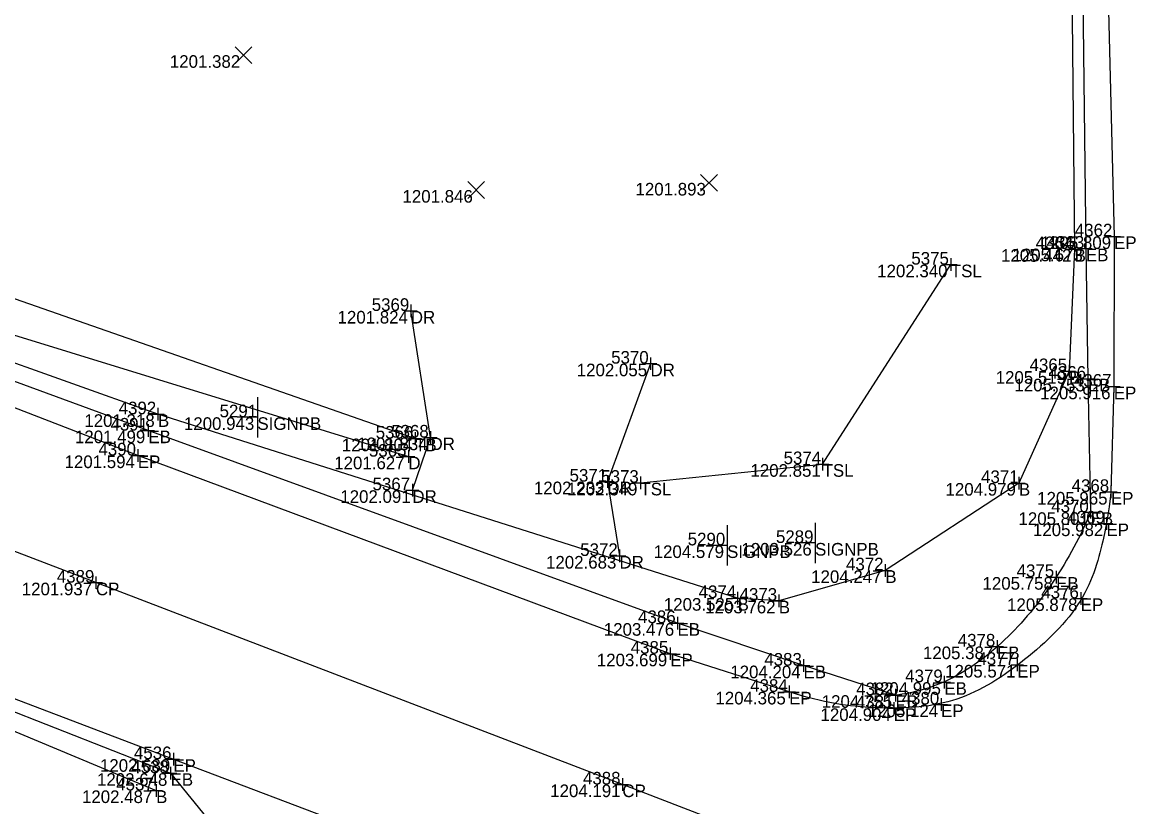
# Model space of a CAD drawing. Extents: x 2044996 to 2050343, y 455232 to 458054.
# Drawn here: x 2047532.5 to 2047620.8, y 457009.8 to 457071.9 of the extents above; entities that cross this region are included whole.
import ezdxf

# ---------------------------------------------------------------- set-up
doc = ezdxf.new("R2010")
doc.units = 0
for name, color, linetype in [('DR_X_Ditch', 7, 'Continuous'), ('DT_X_Contour_Minor', 7, 'Continuous'), ('DT_X_Contour_Text', 7, 'Continuous'), ('DT_X_Spot_Elev', 7, 'Continuous'), ('DT_X_Triangles', 7, 'Continuous'), ('DT_X_Void', 7, 'Continuous'), ('PV_X_COP', 7, 'Continuous'), ('PV_X_Driveway', 7, 'Continuous'), ('PV_X_EOP', 7, 'Continuous'), ('PV_X_Shoulder_Aggregate', 7, 'Continuous'), ('SN_X_Public', 7, 'Continuous'), ('SV_X_Break_Lines', 7, 'Continuous'), ('SV_X_Toe_of_Slope', 7, 'Continuous'), ('SV_X_Top_of_Bank', 7, 'Continuous')]:
    doc.layers.add(name, color=color, linetype=linetype)

msp = doc.modelspace()

# ---------------------------------------------------------------- linework, layer by layer
at = {"layer": 'DR_X_Ditch'}
msp.add_lwpolyline([(2047185.374, 457179.961), (2047230.914, 457162.637), (2047274.771, 457145.428), (2047326.558, 457126.301), (2047357.237, 457113.595), (2047397.496, 457098.279), (2047439.037, 457082.099), (2047486.144, 457064.566), (2047529.75, 457047.807), (2047563.134, 457037.518)], dxfattribs=at)
at = {"layer": 'DT_X_Spot_Elev'}
for p, q in [((2047549.39, 457068.669), (2047550.723, 457070.004)), ((2047549.39, 457070.004), (2047550.723, 457068.669)), ((2047567.839, 457057.981), (2047569.172, 457059.316)), ((2047567.839, 457059.316), (2047569.172, 457057.981)), ((2047586.298, 457058.549), (2047587.631, 457059.884)), ((2047586.298, 457059.884), (2047587.631, 457058.549))]:
    msp.add_line(p, q, dxfattribs=at)
at = {"layer": 'DT_X_Void'}
for p, q in [((2047618.576, 457054.974), (2047619.576, 457054.974)), ((2047619.076, 457055.474), (2047619.076, 457054.474)), ((2047619.076, 457054.974), (2047619.076, 457054.974)), ((2047615.445, 457053.962), (2047616.445, 457053.962)), ((2047615.945, 457054.462), (2047615.945, 457053.462)), ((2047615.945, 457053.962), (2047615.945, 457053.962)), ((2047616.341, 457054.004), (2047617.341, 457054.004)), ((2047616.841, 457054.504), (2047616.841, 457053.504)), ((2047616.841, 457054.004), (2047616.841, 457054.004)), ((2047606.133, 457053.236), (2047606.133, 457052.236)), ((2047605.633, 457052.736), (2047606.633, 457052.736)), ((2047606.133, 457052.736), (2047606.133, 457052.736)), ((2047563.328, 457049.568), (2047563.328, 457048.568)), ((2047562.828, 457049.068), (2047563.828, 457049.068)), ((2047563.328, 457049.068), (2047563.328, 457049.068)), ((2047582.327, 457045.388), (2047582.327, 457044.388)), ((2047581.827, 457044.888), (2047582.827, 457044.888)), ((2047582.327, 457044.888), (2047582.327, 457044.888)), ((2047615.005, 457044.294), (2047616.005, 457044.294)), ((2047615.505, 457044.794), (2047615.505, 457043.794)), ((2047615.505, 457044.294), (2047615.505, 457044.294)), ((2047616.997, 457044.189), (2047616.997, 457043.189)), ((2047616.497, 457043.689), (2047617.497, 457043.689)), ((2047616.997, 457043.689), (2047616.997, 457043.689)), ((2047619.053, 457043.567), (2047619.053, 457042.567)), ((2047618.553, 457043.067), (2047619.553, 457043.067)), ((2047619.053, 457043.067), (2047619.053, 457043.067)), ((2047542.782, 457040.875), (2047543.782, 457040.875)), ((2047543.282, 457041.375), (2047543.282, 457040.375)), ((2047543.282, 457040.875), (2047543.282, 457040.875)), ((2047542.519, 457040.085), (2047542.519, 457039.085)), ((2047542.019, 457039.585), (2047543.019, 457039.585)), ((2047542.519, 457039.585), (2047542.519, 457039.585)), ((2047563.169, 457038.947), (2047564.169, 457038.947)), ((2047563.669, 457039.447), (2047563.669, 457038.447)), ((2047563.669, 457038.947), (2047563.669, 457038.947)), ((2047564.389, 457039.031), (2047565.389, 457039.031)), ((2047564.889, 457039.531), (2047564.889, 457038.531)), ((2047564.889, 457039.031), (2047564.889, 457039.031)), ((2047541.686, 457038.11), (2047541.686, 457037.11)), ((2047563.134, 457038.018), (2047563.134, 457037.018)), ((2047541.186, 457037.61), (2047542.186, 457037.61)), ((2047541.686, 457037.61), (2047541.686, 457037.61)), ((2047562.634, 457037.518), (2047563.634, 457037.518)), ((2047563.134, 457037.518), (2047563.134, 457037.518)), ((2047595.967, 457037.423), (2047595.967, 457036.423)), ((2047595.467, 457036.923), (2047596.467, 457036.923)), ((2047595.967, 457036.923), (2047595.967, 457036.923)), ((2047563.453, 457035.351), (2047563.453, 457034.351)), ((2047578.409, 457035.538), (2047579.409, 457035.538)), ((2047578.909, 457036.038), (2047578.909, 457035.038)), ((2047578.909, 457035.538), (2047578.909, 457035.538)), ((2047581.028, 457035.447), (2047582.028, 457035.447)), ((2047581.528, 457035.947), (2047581.528, 457034.947)), ((2047581.528, 457035.447), (2047581.528, 457035.447)), ((2047611.03, 457035.425), (2047612.03, 457035.425)), ((2047611.53, 457035.925), (2047611.53, 457034.925)), ((2047611.53, 457035.425), (2047611.53, 457035.425)), ((2047562.953, 457034.851), (2047563.953, 457034.851)), ((2047563.453, 457034.851), (2047563.453, 457034.851)), ((2047618.324, 457034.72), (2047619.324, 457034.72)), ((2047618.824, 457035.22), (2047618.824, 457034.22)), ((2047618.824, 457034.72), (2047618.824, 457034.72)), ((2047617.213, 457033.606), (2047617.213, 457032.606)), ((2047616.713, 457033.106), (2047617.713, 457033.106)), ((2047617.213, 457033.106), (2047617.213, 457033.106)), ((2047618.473, 457032.717), (2047618.473, 457031.717)), ((2047617.973, 457032.217), (2047618.973, 457032.217)), ((2047618.473, 457032.217), (2047618.473, 457032.217)), ((2047579.869, 457030.146), (2047579.869, 457029.146)), ((2047579.369, 457029.646), (2047580.369, 457029.646)), ((2047579.869, 457029.646), (2047579.869, 457029.646)), ((2047600.44, 457028.504), (2047601.44, 457028.504)), ((2047600.94, 457029.004), (2047600.94, 457028.004)), ((2047600.94, 457028.504), (2047600.94, 457028.504)), ((2047614.48, 457028.473), (2047614.48, 457027.473)), ((2047537.865, 457027.529), (2047538.865, 457027.529)), ((2047538.365, 457028.029), (2047538.365, 457027.029)), ((2047538.365, 457027.529), (2047538.365, 457027.529)), ((2047613.98, 457027.973), (2047614.98, 457027.973)), ((2047614.48, 457027.973), (2047614.48, 457027.973)), ((2047589.231, 457026.808), (2047589.231, 457025.808)), ((2047592.495, 457026.597), (2047592.495, 457025.597)), ((2047616.429, 457026.783), (2047616.429, 457025.783)), ((2047588.731, 457026.308), (2047589.731, 457026.308)), ((2047589.231, 457026.308), (2047589.231, 457026.308)), ((2047591.995, 457026.097), (2047592.995, 457026.097)), ((2047592.495, 457026.097), (2047592.495, 457026.097)), ((2047615.929, 457026.283), (2047616.929, 457026.283)), ((2047616.429, 457026.283), (2047616.429, 457026.283)), ((2047584.465, 457024.824), (2047584.465, 457023.824)), ((2047583.965, 457024.324), (2047584.965, 457024.324)), ((2047584.465, 457024.324), (2047584.465, 457024.324)), ((2047609.8, 457022.967), (2047609.8, 457021.967)), ((2047583.888, 457022.4), (2047583.888, 457021.4)), ((2047609.3, 457022.467), (2047610.3, 457022.467)), ((2047609.8, 457022.467), (2047609.8, 457022.467)), ((2047583.388, 457021.9), (2047584.388, 457021.9)), ((2047583.888, 457021.9), (2047583.888, 457021.9)), ((2047594.457, 457021.454), (2047594.457, 457020.454)), ((2047611.4, 457021.511), (2047611.4, 457020.511)), ((2047593.957, 457020.954), (2047594.957, 457020.954)), ((2047594.457, 457020.954), (2047594.457, 457020.954)), ((2047610.9, 457021.011), (2047611.9, 457021.011)), ((2047611.4, 457021.011), (2047611.4, 457021.011)), ((2047605.116, 457019.641), (2047606.116, 457019.641)), ((2047605.616, 457020.141), (2047605.616, 457019.141)), ((2047605.616, 457019.641), (2047605.616, 457019.641)), ((2047592.819, 457018.878), (2047593.819, 457018.878)), ((2047593.319, 457019.378), (2047593.319, 457018.378)), ((2047593.319, 457018.878), (2047593.319, 457018.878)), ((2047601.244, 457018.61), (2047602.244, 457018.61)), ((2047601.744, 457019.11), (2047601.744, 457018.11)), ((2047601.744, 457018.61), (2047601.744, 457018.61)), ((2047601.61, 457018.069), (2047601.61, 457017.069)), ((2047604.857, 457017.875), (2047605.857, 457017.875)), ((2047605.357, 457018.375), (2047605.357, 457017.375)), ((2047605.357, 457017.875), (2047605.357, 457017.875)), ((2047601.11, 457017.569), (2047602.11, 457017.569)), ((2047601.61, 457017.569), (2047601.61, 457017.569)), ((2047544.001, 457013.539), (2047545.001, 457013.539)), ((2047544.501, 457014.039), (2047544.501, 457013.039)), ((2047544.501, 457013.539), (2047544.501, 457013.539)), ((2047543.785, 457012.426), (2047544.785, 457012.426)), ((2047544.285, 457012.926), (2047544.285, 457011.926)), ((2047544.285, 457012.426), (2047544.285, 457012.426)), ((2047543.137, 457011.562), (2047543.137, 457010.562)), ((2047579.593, 457011.532), (2047580.593, 457011.532)), ((2047580.093, 457012.032), (2047580.093, 457011.032)), ((2047580.093, 457011.532), (2047580.093, 457011.532)), ((2047542.637, 457011.062), (2047543.637, 457011.062)), ((2047543.137, 457011.062), (2047543.137, 457011.062))]:
    msp.add_line(p, q, dxfattribs=at)
at = {"layer": 'PV_X_COP'}
msp.add_lwpolyline([(2047612.389, 456999.113), (2047580.093, 457011.532), (2047538.365, 457027.529), (2047496.013, 457043.827), (2047451.821, 457060.105), (2047409.771, 457076.509), (2047364.773, 457093.969), (2047313.939, 457114.01), (2047268.544, 457131.55), (2047222.122, 457149.924), (2047177.697, 457167.482), (2047132.784, 457184.838), (2047088.938, 457201.347), (2047045.018, 457217.225), (2047000.472, 457231.972), (2046961.141, 457242.698), (2046914.32, 457253.597), (2046869.816, 457261.807), (2046824.048, 457268.962), (2046778.684, 457274.618), (2046733.923, 457279.831), (2046684.611, 457284.915), (2046649.606, 457288.121)], dxfattribs=at)
at = {"layer": 'PV_X_Driveway'}
for points in [[(2047563.453, 457034.851), (2047564.889, 457039.031), (2047563.328, 457049.068)], [(2047582.327, 457044.888), (2047578.909, 457035.538), (2047579.869, 457029.646)]]:
    msp.add_lwpolyline(points, dxfattribs=at)
at = {"layer": 'PV_X_EOP'}
for p, q in [((2047617.938, 457101.121), (2047619.076, 457054.974)), ((2047619.076, 457054.974), (2047619.053, 457043.067)), ((2047541.686, 457037.61), (2047500.507, 457053.509)), ((2047619.053, 457043.067), (2047618.824, 457034.72)), ((2047583.888, 457021.9), (2047541.686, 457037.61)), ((2047522.952, 457021.734), (2047544.501, 457013.539)), ((2047593.319, 457018.878), (2047583.888, 457021.9)), ((2047544.501, 457013.539), (2047576.047, 457001.627))]:
    msp.add_line(p, q, dxfattribs=at)
msp.add_open_spline([(2047618.824, 457034.72), (2047618.752, 457033.875), (2047618.326, 457030.993), (2047616.779, 457025.658), (2047611.674, 457020.928), (2047606.455, 457017.69), (2047600.021, 457017.441), (2047596.065, 457017.983), (2047593.319, 457018.878)], degree=3, dxfattribs=at)
at = {"layer": 'PV_X_Shoulder_Aggregate'}
for p, q in [((2047616.273, 457101.148), (2047616.841, 457054.004)), ((2047542.519, 457039.585), (2047500.224, 457055.092)), ((2047616.841, 457054.004), (2047616.997, 457043.689)), ((2047616.997, 457043.689), (2047617.213, 457033.106)), ((2047584.465, 457024.324), (2047542.519, 457039.585)), ((2047594.457, 457020.954), (2047584.465, 457024.324)), ((2047522.981, 457020.798), (2047544.285, 457012.426)), ((2047601.744, 457018.61), (2047594.457, 457020.954)), ((2047544.285, 457012.426), (2047547.496, 457008.476))]:
    msp.add_line(p, q, dxfattribs=at)
msp.add_open_spline([(2047617.213, 457033.106), (2047616.455, 457031.29), (2047614.405, 457027.47), (2047610.524, 457022.778), (2047606.036, 457019.517), (2047603.117, 457018.776), (2047601.744, 457018.61)], degree=3, dxfattribs=at)
at = {"layer": 'SN_X_Public'}
for p, q in [((2047551.166, 457042.237), (2047551.166, 457039.037)), ((2047551.166, 457040.637), (2047549.566, 457040.637)), ((2047588.395, 457032.084), (2047588.395, 457028.884)), ((2047595.37, 457032.275), (2047595.37, 457029.075)), ((2047588.395, 457030.484), (2047586.795, 457030.484)), ((2047595.37, 457030.675), (2047593.77, 457030.675))]:
    msp.add_line(p, q, dxfattribs=at)
at = {"layer": 'SV_X_Break_Lines'}
for points in [[(2047609.606, 457393.106), (2047610.315, 457343.259), (2047611.064, 457296.497), (2047612.477, 457248.738), (2047612.892, 457199.618), (2047614.532, 457148.61), (2047615.457, 457101.16), (2047615.945, 457053.962), (2047615.505, 457044.294), (2047611.53, 457035.425), (2047600.94, 457028.504), (2047592.495, 457026.097), (2047589.231, 457026.308), (2047543.282, 457040.875), (2047500.592, 457056.092), (2047456.763, 457072.198), (2047414.816, 457088.31), (2047369.13, 457105.973), (2047320.737, 457125.374), (2047273.194, 457143.598), (2047227.373, 457161.688), (2047183.553, 457178.86)], [(2046644.987, 457274.789), (2046684.792, 457271.319), (2046731.453, 457265.984), (2046776.364, 457261.919), (2046820.966, 457255.959), (2046865.167, 457248.932), (2046910.617, 457240.567), (2046953.493, 457230.478), (2046996.082, 457218.339), (2047041.047, 457204.359), (2047086.235, 457188.112), (2047130.382, 457171.332), (2047171.934, 457154.515), (2047216.747, 457137.04), (2047260.77, 457120.173), (2047304.384, 457102.936), (2047349.358, 457085.134), (2047391.243, 457069.284), (2047438.053, 457051.139), (2047480.2, 457035.909), (2047522.535, 457019.675), (2047543.137, 457011.062)]]:
    msp.add_lwpolyline(points, dxfattribs=at)
at = {"layer": 'SV_X_Toe_of_Slope'}
msp.add_lwpolyline([(2047581.528, 457035.447), (2047595.967, 457036.923), (2047606.133, 457052.736)], dxfattribs=at)
at = {"layer": 'SV_X_Top_of_Bank'}
msp.add_lwpolyline([(2046651.928, 457311.459), (2046700.585, 457305.724), (2046746.85, 457300.374), (2046773.129, 457296.21), (2046810.211, 457291.653), (2046866.306, 457282.869), (2046913.133, 457276.049), (2046946.872, 457270.498), (2046956.838, 457268.663), (2047005.284, 457255.726), (2047019.972, 457251.509), (2047064.03, 457231.461), (2047107.634, 457215.293), (2047146.988, 457200.965), (2047188.634, 457185.752), (2047229.807, 457169.99), (2047277.499, 457150.033), (2047328.362, 457129.782), (2047359.214, 457118.113), (2047442.139, 457085.967), (2047488.032, 457067.346), (2047530.827, 457050.419), (2047563.669, 457038.947)], dxfattribs=at)

# ---------------------------------------------------------------- texts
at = {"layer": 'DT_X_Contour_Minor'}
for s, p in [('1201.382', (2047544.224, 457068.337)), ('1201.893', (2047581.138, 457058.216)), ('1201.846', (2047562.665, 457057.648)), ('1205.809', (2047613.258, 457053.974)), ('1205.442', (2047610.112, 457052.962)), ('1205.673', (2047611.015, 457053.004)), ('1202.340', (2047600.295, 457051.736)), ('1201.824', (2047557.52, 457048.068)), ('1202.055', (2047576.48, 457043.888)), ('1205.519', (2047609.687, 457043.294)), ('1205.753', (2047611.171, 457042.689)), ('1205.916', (2047613.212, 457042.067)), ('1201.318', (2047537.446, 457039.875)), ('1200.943', (2047545.34, 457039.637)), ('1201.499', (2047536.701, 457038.585)), ('1201.804', (2047557.861, 457037.947)), ('1201.834', (2047559.081, 457038.031)), ('1201.594', (2047535.878, 457036.61)), ('1201.627', (2047557.255, 457036.518)), ('1202.851', (2047590.249, 457035.923)), ('1202.233', (2047573.083, 457034.538)), ('1202.349', (2047575.71, 457034.447)), ('1204.979', (2047605.713, 457034.425)), ('1202.091', (2047557.736, 457033.851)), ('1205.965', (2047612.977, 457033.72)), ('1205.801', (2047611.496, 457032.106)), ('1205.982', (2047612.64, 457031.217)), ('1204.579', (2047582.577, 457029.484)), ('1203.526', (2047589.529, 457029.675)), ('1202.683', (2047574.043, 457028.646)), ('1204.247', (2047595.061, 457027.504)), ('1201.937', (2047532.486, 457026.529)), ('1205.758', (2047608.644, 457026.973)), ('1203.525', (2047583.383, 457025.308)), ('1203.762', (2047586.662, 457025.097)), ('1205.878', (2047610.593, 457025.283)), ('1203.476', (2047578.625, 457023.324)), ('1205.387', (2047603.921, 457021.467)), ('1203.699', (2047578.071, 457020.9)), ('1204.204', (2047588.649, 457019.954)), ('1205.571', (2047605.683, 457020.011)), ('1204.995', (2047599.768, 457018.641)), ('1204.365', (2047587.472, 457017.878)), ('1204.755', (2047595.897, 457017.61)), ('1205.124', (2047599.549, 457016.875)), ('1204.904', (2047595.802, 457016.569)), ('1202.689', (2047538.683, 457012.539)), ('1202.648', (2047538.449, 457011.426)), ('1204.191', (2047574.376, 457010.532)), ('1202.487', (2047537.257, 457010.062))]:
    msp.add_text(s, height=1, dxfattribs=at).set_placement(p)
at = {"layer": 'DT_X_Contour_Text'}
for s, p in [('EP', (2047619.076, 457053.974)), ('B', (2047615.945, 457052.962)), ('EB', (2047616.841, 457053.004)), ('TSL', (2047606.133, 457051.736)), ('DR', (2047563.328, 457048.068)), ('DR', (2047582.327, 457043.888)), ('B', (2047615.505, 457043.294)), ('EB', (2047616.997, 457042.689)), ('EP', (2047619.053, 457042.067)), ('B', (2047543.282, 457039.875)), ('SIGNPB', (2047551.166, 457039.637)), ('EB', (2047542.519, 457038.585)), ('TB', (2047563.669, 457037.947)), ('DR', (2047564.889, 457038.031)), ('EP', (2047541.686, 457036.61)), ('D', (2047563.134, 457036.518)), ('TSL', (2047595.967, 457035.923)), ('DR', (2047578.909, 457034.538)), ('TSL', (2047581.528, 457034.447)), ('B', (2047611.53, 457034.425)), ('DR', (2047563.453, 457033.851)), ('EP', (2047618.824, 457033.72)), ('EB', (2047617.213, 457032.106)), ('EP', (2047618.473, 457031.217)), ('SIGNPB', (2047588.395, 457029.484)), ('SIGNPB', (2047595.37, 457029.675)), ('DR', (2047579.869, 457028.646)), ('B', (2047600.94, 457027.504)), ('CP', (2047538.365, 457026.529)), ('EB', (2047614.48, 457026.973)), ('B', (2047589.231, 457025.308)), ('B', (2047592.495, 457025.097)), ('EP', (2047616.429, 457025.283)), ('EB', (2047584.465, 457023.324)), ('EB', (2047609.8, 457021.467)), ('EP', (2047583.888, 457020.9)), ('EB', (2047594.457, 457019.954)), ('EP', (2047611.4, 457020.011)), ('EB', (2047605.616, 457018.641)), ('EP', (2047593.319, 457017.878)), ('EB', (2047601.744, 457017.61)), ('EP', (2047605.357, 457016.875)), ('EP', (2047601.61, 457016.569)), ('EP', (2047544.501, 457012.539)), ('EB', (2047544.285, 457011.426)), ('CP', (2047580.093, 457010.532)), ('B', (2047543.137, 457010.062))]:
    msp.add_text(s, height=1, dxfattribs=at).set_placement(p)
at = {"layer": 'DT_X_Triangles'}
for s, p in [('4362', (2047615.961, 457054.974)), ('4364', (2047612.855, 457053.962)), ('4363', (2047613.733, 457054.004)), ('5375', (2047603.003, 457052.736)), ('5369', (2047560.228, 457049.068)), ('5370', (2047579.208, 457044.888)), ('4365', (2047612.375, 457044.294)), ('4366', (2047613.874, 457043.689)), ('4367', (2047615.892, 457043.067)), ('4392', (2047540.167, 457040.875)), ('5291', (2047548.167, 457040.637)), ('4391', (2047539.52, 457039.585)), ('5366', (2047560.546, 457038.947)), ('5368', (2047561.771, 457039.031)), ('4390', (2047538.566, 457037.61)), ('5365', (2047560.005, 457037.518)), ('5374', (2047592.877, 457036.923)), ('5371', (2047575.91, 457035.538)), ('5373', (2047578.42, 457035.447)), ('4371', (2047608.531, 457035.425)), ('5367', (2047560.292, 457034.851)), ('4368', (2047615.706, 457034.72)), ('4370', (2047614.093, 457033.106)), ('4369', (2047615.373, 457032.217)), ('5290', (2047585.275, 457030.484)), ('5289', (2047592.27, 457030.675)), ('5372', (2047576.754, 457029.646)), ('4372', (2047597.825, 457028.504)), ('4389', (2047535.266, 457027.529)), ('4375', (2047611.35, 457027.973)), ('4374', (2047586.141, 457026.308)), ('4373', (2047589.387, 457026.097)), ('4376', (2047613.306, 457026.283)), ('4386', (2047581.343, 457024.324)), ('4378', (2047606.682, 457022.467)), ('4385', (2047580.759, 457021.9)), ('4383', (2047591.348, 457020.954)), ('4377', (2047608.239, 457021.011)), ('4379', (2047602.516, 457019.641)), ('4384', (2047590.229, 457018.878)), ('4382', (2047598.629, 457018.61)), ('4381', (2047598.611, 457017.569)), ('4380', (2047602.237, 457017.875)), ('4536', (2047541.378, 457013.539)), ('4538', (2047541.167, 457012.426)), ('4388', (2047576.975, 457011.532)), ('4537', (2047539.975, 457011.062))]:
    msp.add_text(s, height=1, dxfattribs=at).set_placement(p)

doc.saveas('drawing.dxf')
